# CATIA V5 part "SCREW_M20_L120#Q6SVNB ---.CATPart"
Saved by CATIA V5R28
Part number: SCREW_M20_L120#Q6SVMU
Revision: ---
Nomenclature: _
Description: SCREW_M20_L120
Property "AT": "PD"
Property "REP": "CM"
Property "External Part ID": "_"
Property "Description Modification": "FDRModel"
Property "PREF": "Y"
Property "LONG": "_"
Property "PBS 1": "24"
Property "PBS 2": "CR"
Property "PBS 3": "LC"
Property "DEPT": "_"
Property "DIVN": "_"
Property "GROUP": "_"
Property "UNIT": "_"
Property "PARTY": "_"
Property "RO": "---"
Property "RE": "SEKACHI"
Property "PRO": "---"
Property "Change Type": "Major"
Property "Maturity Level": "CD"
Property "Export Number": "_"
Property "Description Documents": "_"
Property "BOM": "_"
Property "ID": "Q6SVMU"
Property "User In Enovia": "VAUQUEJ"
Property "Object Type": "_"
Property "CADENAS_ID": "_"
Property "Life Cycle Status": "Approved"
Bounding box of the stored display mesh (mm): x -17.321 to 17.321, y -20 to 20, z -120 to 14
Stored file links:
  C:\Users\pandeym\Desktop\__TCPH\SCREW_M20_L120#Q6SVNB ---.CATPart
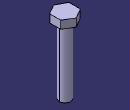
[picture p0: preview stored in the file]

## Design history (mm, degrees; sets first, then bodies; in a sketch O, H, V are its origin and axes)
Body1 (main body)
  Sketch1 on xy-plane, origin (0, 0, 0), H (1, 0, 0), V (0, 1, 0)
    circle A1 centre (0, 0) radius 10
    radius A1 = 10
  Pad1: profile Sketch1, direction (0, 0, -1), length 120
  Sketch2 on start face of Pad1, origin (0, 0, 0), H (1, 0, 0), V (0, 1, 0)
    point P1 (17.3205, -10)
    point P2 (17.3205, 10)
    point P3 (0, 20)
    point P4 (-17.3205, 10)
    point P5 (-17.3205, -10)
    point P6 (0, -20)
    point P7 (17.3205, 0)
    line L1 (17.3205, -10) -> (17.3205, 10)
    line L2 (17.3205, 10) -> (0, 20)
    line L3 (0, 20) -> (-17.3205, 10)
    line L4 (-17.3205, 10) -> (-17.3205, -10)
    line L5 (-17.3205, -10) -> (0, -20)
    line L6 (0, -20) -> (17.3205, -10)
    construction line L7 (0, 0) -> (17.3205, 0)
    construction circle A1 centre (0, 0) radius 20
    construction arc A2 centre (-17.3205, -10) radius 20 from (-17.3205, 10) to (0, -20) cw
    construction arc A3 centre (17.3205, 10) radius 20 from (0, 20) to (17.3205, -10) ccw
    length L1 = 20
    horizontal: L7 H
    coincidence: A1 P1, A1 P2, A1 P3, A1 P4, A1 P5, A1 P6, A2 O, A3 O
    midpoint: P7 L1
    parallelism: L1 L4
  Pad2: profile Sketch2, direction (0, 0, 1), length 14
  Thread1: diameter 20, depth 100, pitch 1, on face of Pad1 from Sketch1.A1, from end face of Pad1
